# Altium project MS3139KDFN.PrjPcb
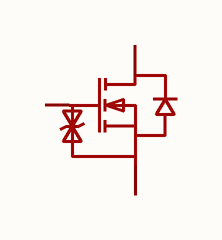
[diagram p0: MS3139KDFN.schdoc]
1 sheet, 1 parts. Net scope: global (net labels, ports and power ports of the same name join across sheets).

## Sheet MS3139KDFN.schdoc
size 127 x 101 mm

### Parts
U?  ms3139kdfn  [DFN1006-3_L1.0-W0.6-LS1.0-BR]  (value not drawn)

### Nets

Not connected (* = marked no-connect by the designer): U? 1(G) 2(D) 3(S)

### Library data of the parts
U? = ms3139kdfn: 数量:1个P沟道;漏源电压(Vdss):20V;连续漏极电流(Id):600mA;导通电阻(RDS(on)):650mΩ@4.5V;耗散功率(Pd):450mW;阈值电压(Vgs(th)):1V@250uA;; Manufacturer: MSKSEMI(美森科); AddInBom: yes; ModelId: cc686921d11847a99f974ae407b58fda; ModelName: DFN1006-3L_L1.0-W0.6-H0.4-LS1.0-BR; ModelTransform: 40.1574,24.4094,0,180,0,0,0,0,0; Number: 1个P沟道; Drain to Source Voltage: 20V; Current - Continuous Drain(Id): 600mA; Pd - Power Dissipation: 450mW; Gate Charge(Qg): 1nC@4.5V; Reverse Transfer Capacitance (Crss@Vds): 15pF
